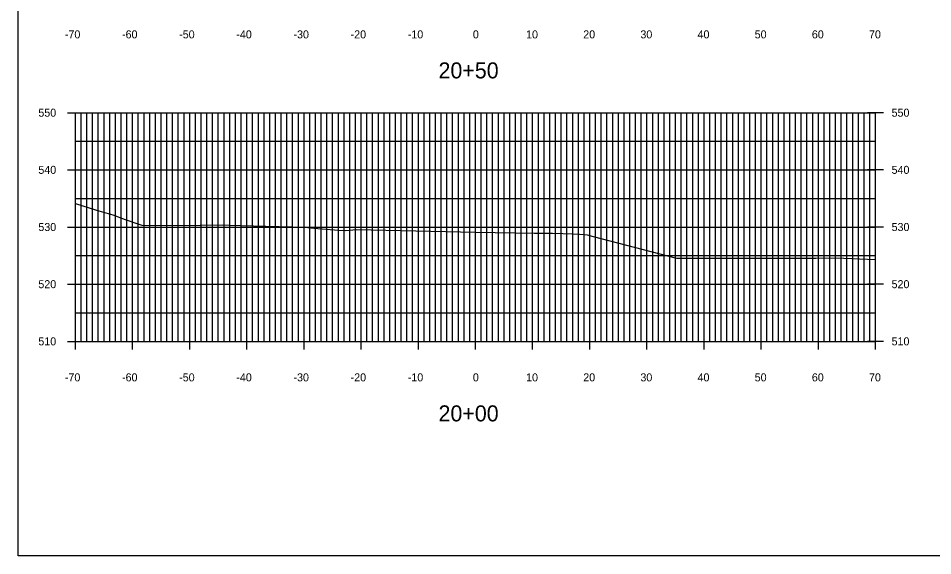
# Model space of a CAD drawing. Extents: x 1509063 to 1512863, y 401160 to 402918.
# Drawn here: x 1510250.9 to 1510410.9, y 402707.9 to 402801.9 of the extents above; entities that cross this region are included whole.
import ezdxf

# ---------------------------------------------------------------- set-up
doc = ezdxf.new("R2010")
doc.units = 0
for name, color, linetype in [('NBL1', 7, 'Continuous'), ('XAX_P', 7, 'Continuous'), ('XAXTIC_P', 7, 'Continuous'), ('XAXTXT_P_T', 7, 'Continuous'), ('XGL_P', 7, 'Continuous'), ('XSLOG', 7, 'Continuous')]:
    doc.layers.add(name, color=color, linetype=linetype)

msp = doc.modelspace()

# ---------------------------------------------------------------- linework, layer by layer
at = {"layer": 'NBL1'}
msp.add_lwpolyline([(1510570.91, 402707.91), (1510250.91, 402707.91), (1510250.91, 402917.91), (1510570.91, 402917.91)], close=True, dxfattribs=at)
at = {"layer": 'XAX_P'}
for p, q in [((1510260.91, 402745.41), (1510260.91, 402785.41)), ((1510330.91, 402745.41), (1510330.91, 402785.41)), ((1510400.91, 402745.41), (1510400.91, 402785.41)), ((1510260.91, 402745.41), (1510400.91, 402745.41))]:
    msp.add_line(p, q, dxfattribs=at)
at = {"layer": 'XAXTIC_P'}
for p, q in [((1510259.51, 402785.41), (1510262.31, 402785.41)), ((1510329.51, 402785.41), (1510332.31, 402785.41)), ((1510402.31, 402785.41), (1510399.51, 402785.41)), ((1510259.51, 402775.41), (1510262.31, 402775.41)), ((1510329.51, 402775.41), (1510332.31, 402775.41)), ((1510402.31, 402775.41), (1510399.51, 402775.41)), ((1510259.51, 402765.41), (1510262.31, 402765.41)), ((1510329.51, 402765.41), (1510332.31, 402765.41)), ((1510402.31, 402765.41), (1510399.51, 402765.41)), ((1510259.51, 402755.41), (1510262.31, 402755.41)), ((1510329.51, 402755.41), (1510332.31, 402755.41)), ((1510402.31, 402755.41), (1510399.51, 402755.41)), ((1510260.91, 402744.01), (1510260.91, 402746.81)), ((1510270.91, 402744.01), (1510270.91, 402746.81)), ((1510280.91, 402744.01), (1510280.91, 402746.81)), ((1510290.91, 402744.01), (1510290.91, 402746.81)), ((1510300.91, 402744.01), (1510300.91, 402746.81)), ((1510310.91, 402744.01), (1510310.91, 402746.81)), ((1510320.91, 402744.01), (1510320.91, 402746.81)), ((1510330.91, 402744.01), (1510330.91, 402746.81)), ((1510340.91, 402744.01), (1510340.91, 402746.81)), ((1510350.91, 402744.01), (1510350.91, 402746.81)), ((1510360.91, 402744.01), (1510360.91, 402746.81)), ((1510370.91, 402744.01), (1510370.91, 402746.81)), ((1510380.91, 402744.01), (1510380.91, 402746.81)), ((1510390.91, 402744.01), (1510390.91, 402746.81)), ((1510400.91, 402744.01), (1510400.91, 402746.81)), ((1510259.51, 402745.41), (1510262.31, 402745.41)), ((1510329.51, 402745.41), (1510332.31, 402745.41)), ((1510402.31, 402745.41), (1510399.51, 402745.41))]:
    msp.add_line(p, q, dxfattribs=at)
at = {"layer": 'XGL_P'}
for p, q in [((1510260.91, 402785.41), (1510400.91, 402785.41)), ((1510260.91, 402745.41), (1510260.91, 402785.41)), ((1510261.91, 402745.41), (1510261.91, 402785.41)), ((1510262.91, 402745.41), (1510262.91, 402785.41)), ((1510263.91, 402745.41), (1510263.91, 402785.41)), ((1510264.91, 402745.41), (1510264.91, 402785.41)), ((1510265.91, 402745.41), (1510265.91, 402785.41)), ((1510266.91, 402745.41), (1510266.91, 402785.41)), ((1510267.91, 402745.41), (1510267.91, 402785.41)), ((1510268.91, 402745.41), (1510268.91, 402785.41)), ((1510269.91, 402745.41), (1510269.91, 402785.41)), ((1510270.91, 402745.41), (1510270.91, 402785.41)), ((1510271.91, 402745.41), (1510271.91, 402785.41)), ((1510272.91, 402745.41), (1510272.91, 402785.41)), ((1510273.91, 402745.41), (1510273.91, 402785.41)), ((1510274.91, 402745.41), (1510274.91, 402785.41)), ((1510275.91, 402745.41), (1510275.91, 402785.41)), ((1510276.91, 402745.41), (1510276.91, 402785.41)), ((1510277.91, 402745.41), (1510277.91, 402785.41)), ((1510278.91, 402745.41), (1510278.91, 402785.41)), ((1510279.91, 402745.41), (1510279.91, 402785.41)), ((1510280.91, 402745.41), (1510280.91, 402785.41)), ((1510281.91, 402745.41), (1510281.91, 402785.41)), ((1510282.91, 402745.41), (1510282.91, 402785.41)), ((1510283.91, 402745.41), (1510283.91, 402785.41)), ((1510284.91, 402745.41), (1510284.91, 402785.41)), ((1510285.91, 402745.41), (1510285.91, 402785.41)), ((1510286.91, 402745.41), (1510286.91, 402785.41)), ((1510287.91, 402745.41), (1510287.91, 402785.41)), ((1510288.91, 402745.41), (1510288.91, 402785.41)), ((1510289.91, 402745.41), (1510289.91, 402785.41)), ((1510290.91, 402745.41), (1510290.91, 402785.41)), ((1510291.91, 402745.41), (1510291.91, 402785.41)), ((1510292.91, 402745.41), (1510292.91, 402785.41)), ((1510293.91, 402745.41), (1510293.91, 402785.41)), ((1510294.91, 402745.41), (1510294.91, 402785.41)), ((1510295.91, 402745.41), (1510295.91, 402785.41)), ((1510296.91, 402745.41), (1510296.91, 402785.41)), ((1510297.91, 402745.41), (1510297.91, 402785.41)), ((1510298.91, 402745.41), (1510298.91, 402785.41)), ((1510299.91, 402745.41), (1510299.91, 402785.41)), ((1510300.91, 402745.41), (1510300.91, 402785.41)), ((1510301.91, 402745.41), (1510301.91, 402785.41)), ((1510302.91, 402745.41), (1510302.91, 402785.41)), ((1510303.91, 402745.41), (1510303.91, 402785.41)), ((1510304.91, 402745.41), (1510304.91, 402785.41)), ((1510305.91, 402745.41), (1510305.91, 402785.41)), ((1510306.91, 402745.41), (1510306.91, 402785.41)), ((1510307.91, 402745.41), (1510307.91, 402785.41)), ((1510308.91, 402745.41), (1510308.91, 402785.41)), ((1510309.91, 402745.41), (1510309.91, 402785.41)), ((1510310.91, 402745.41), (1510310.91, 402785.41)), ((1510311.91, 402745.41), (1510311.91, 402785.41)), ((1510312.91, 402745.41), (1510312.91, 402785.41)), ((1510313.91, 402745.41), (1510313.91, 402785.41)), ((1510314.91, 402745.41), (1510314.91, 402785.41)), ((1510315.91, 402745.41), (1510315.91, 402785.41)), ((1510316.91, 402745.41), (1510316.91, 402785.41)), ((1510317.91, 402745.41), (1510317.91, 402785.41)), ((1510318.91, 402745.41), (1510318.91, 402785.41)), ((1510319.91, 402745.41), (1510319.91, 402785.41)), ((1510320.91, 402745.41), (1510320.91, 402785.41)), ((1510321.91, 402745.41), (1510321.91, 402785.41)), ((1510322.91, 402745.41), (1510322.91, 402785.41)), ((1510323.91, 402745.41), (1510323.91, 402785.41)), ((1510324.91, 402745.41), (1510324.91, 402785.41)), ((1510325.91, 402745.41), (1510325.91, 402785.41)), ((1510326.91, 402745.41), (1510326.91, 402785.41)), ((1510327.91, 402745.41), (1510327.91, 402785.41)), ((1510328.91, 402745.41), (1510328.91, 402785.41)), ((1510329.91, 402745.41), (1510329.91, 402785.41)), ((1510330.91, 402745.41), (1510330.91, 402785.41)), ((1510331.91, 402745.41), (1510331.91, 402785.41)), ((1510332.91, 402745.41), (1510332.91, 402785.41)), ((1510333.91, 402745.41), (1510333.91, 402785.41)), ((1510334.91, 402745.41), (1510334.91, 402785.41)), ((1510335.91, 402745.41), (1510335.91, 402785.41)), ((1510336.91, 402745.41), (1510336.91, 402785.41)), ((1510337.91, 402745.41), (1510337.91, 402785.41)), ((1510338.91, 402745.41), (1510338.91, 402785.41)), ((1510339.91, 402745.41), (1510339.91, 402785.41)), ((1510340.91, 402745.41), (1510340.91, 402785.41)), ((1510341.91, 402745.41), (1510341.91, 402785.41)), ((1510342.91, 402745.41), (1510342.91, 402785.41)), ((1510343.91, 402745.41), (1510343.91, 402785.41)), ((1510344.91, 402745.41), (1510344.91, 402785.41)), ((1510345.91, 402745.41), (1510345.91, 402785.41)), ((1510346.91, 402745.41), (1510346.91, 402785.41)), ((1510347.91, 402745.41), (1510347.91, 402785.41)), ((1510348.91, 402745.41), (1510348.91, 402785.41)), ((1510349.91, 402745.41), (1510349.91, 402785.41)), ((1510350.91, 402745.41), (1510350.91, 402785.41)), ((1510351.91, 402745.41), (1510351.91, 402785.41)), ((1510352.91, 402745.41), (1510352.91, 402785.41)), ((1510353.91, 402745.41), (1510353.91, 402785.41)), ((1510354.91, 402745.41), (1510354.91, 402785.41)), ((1510355.91, 402745.41), (1510355.91, 402785.41)), ((1510356.91, 402745.41), (1510356.91, 402785.41)), ((1510357.91, 402745.41), (1510357.91, 402785.41)), ((1510358.91, 402745.41), (1510358.91, 402785.41)), ((1510359.91, 402745.41), (1510359.91, 402785.41)), ((1510360.91, 402745.41), (1510360.91, 402785.41)), ((1510361.91, 402745.41), (1510361.91, 402785.41)), ((1510362.91, 402745.41), (1510362.91, 402785.41)), ((1510363.91, 402745.41), (1510363.91, 402785.41)), ((1510364.91, 402745.41), (1510364.91, 402785.41)), ((1510365.91, 402745.41), (1510365.91, 402785.41)), ((1510366.91, 402745.41), (1510366.91, 402785.41)), ((1510367.91, 402745.41), (1510367.91, 402785.41)), ((1510368.91, 402745.41), (1510368.91, 402785.41)), ((1510369.91, 402745.41), (1510369.91, 402785.41)), ((1510370.91, 402745.41), (1510370.91, 402785.41)), ((1510371.91, 402745.41), (1510371.91, 402785.41)), ((1510372.91, 402745.41), (1510372.91, 402785.41)), ((1510373.91, 402745.41), (1510373.91, 402785.41)), ((1510374.91, 402745.41), (1510374.91, 402785.41)), ((1510375.91, 402745.41), (1510375.91, 402785.41)), ((1510376.91, 402745.41), (1510376.91, 402785.41)), ((1510377.91, 402745.41), (1510377.91, 402785.41)), ((1510378.91, 402745.41), (1510378.91, 402785.41)), ((1510379.91, 402745.41), (1510379.91, 402785.41)), ((1510380.91, 402745.41), (1510380.91, 402785.41)), ((1510381.91, 402745.41), (1510381.91, 402785.41)), ((1510382.91, 402745.41), (1510382.91, 402785.41)), ((1510383.91, 402745.41), (1510383.91, 402785.41)), ((1510384.91, 402745.41), (1510384.91, 402785.41)), ((1510385.91, 402745.41), (1510385.91, 402785.41)), ((1510386.91, 402745.41), (1510386.91, 402785.41)), ((1510387.91, 402745.41), (1510387.91, 402785.41)), ((1510388.91, 402745.41), (1510388.91, 402785.41)), ((1510389.91, 402745.41), (1510389.91, 402785.41)), ((1510390.91, 402745.41), (1510390.91, 402785.41)), ((1510391.91, 402745.41), (1510391.91, 402785.41)), ((1510392.91, 402745.41), (1510392.91, 402785.41)), ((1510393.91, 402745.41), (1510393.91, 402785.41)), ((1510394.91, 402745.41), (1510394.91, 402785.41)), ((1510395.91, 402745.41), (1510395.91, 402785.41)), ((1510396.91, 402745.41), (1510396.91, 402785.41)), ((1510397.91, 402745.41), (1510397.91, 402785.41)), ((1510398.91, 402745.41), (1510398.91, 402785.41)), ((1510399.91, 402745.41), (1510399.91, 402785.41)), ((1510400.91, 402745.41), (1510400.91, 402785.41)), ((1510260.91, 402780.41), (1510400.91, 402780.41)), ((1510260.91, 402775.41), (1510400.91, 402775.41)), ((1510260.91, 402770.41), (1510400.91, 402770.41)), ((1510260.91, 402765.41), (1510400.91, 402765.41)), ((1510260.91, 402760.41), (1510400.91, 402760.41)), ((1510260.91, 402755.41), (1510400.91, 402755.41)), ((1510260.91, 402750.41), (1510400.91, 402750.41)), ((1510260.91, 402745.41), (1510400.91, 402745.41))]:
    msp.add_line(p, q, dxfattribs=at)
at = {"layer": 'XSLOG'}
msp.add_lwpolyline([(1510260.91, 402769.52), (1510264.62, 402768.35), (1510267.48, 402767.54), (1510269.63, 402766.73), (1510271.63, 402766.03), (1510272.5, 402765.75), (1510272.98, 402765.65), (1510282.73, 402765.76), (1510286.61, 402765.8), (1510287.8, 402765.75), (1510294.23, 402765.57), (1510298.97, 402765.42), (1510300.32, 402765.38), (1510301.07, 402765.36), (1510302.6, 402765.2), (1510306.92, 402764.87), (1510308.22, 402764.8), (1510310.05, 402764.99), (1510330.91, 402764.51), (1510341.22, 402764.36), (1510344.36, 402764.32), (1510347.97, 402764.2), (1510349.08, 402764.17), (1510350.46, 402764.06), (1510351.5, 402763.75), (1510366.06, 402759.97), (1510370.72, 402759.98), (1510390.43, 402759.99), (1510393.93, 402760), (1510400.91, 402759.74)], dxfattribs=at)

# ---------------------------------------------------------------- texts
at = {"layer": 'XAXTXT_P_T'}
for s, height, p in [('-70', 1.4, (1510259.06, 402798.41)), ('-60', 1.4, (1510269.06, 402798.41)), ('-50', 1.4, (1510279.06, 402798.41)), ('-40', 1.4, (1510289.06, 402798.41)), ('-30', 1.4, (1510299.06, 402798.41)), ('-20', 1.4, (1510309.06, 402798.41)), ('-10', 1.4, (1510319.06, 402798.41)), ('0', 1.4, (1510330.45, 402798.41)), ('10', 1.4, (1510339.76, 402798.41)), ('20', 1.4, (1510349.76, 402798.41)), ('30', 1.4, (1510359.76, 402798.41)), ('40', 1.4, (1510369.76, 402798.41)), ('50', 1.4, (1510379.76, 402798.41)), ('60', 1.4, (1510389.76, 402798.41)), ('70', 1.4, (1510399.76, 402798.41)), ('20+50', 2.8, (1510324.44, 402791.41)), ('550', 1.4, (1510254.42, 402784.71)), ('550', 1.4, (1510403.71, 402784.71)), ('540', 1.4, (1510254.42, 402774.71)), ('540', 1.4, (1510403.71, 402774.71)), ('530', 1.4, (1510254.42, 402764.71)), ('530', 1.4, (1510403.71, 402764.71)), ('520', 1.4, (1510254.42, 402754.71)), ('520', 1.4, (1510403.71, 402754.71)), ('510', 1.4, (1510254.42, 402744.71)), ('510', 1.4, (1510403.71, 402744.71)), ('-70', 1.4, (1510259.06, 402738.41)), ('-60', 1.4, (1510269.06, 402738.41)), ('-50', 1.4, (1510279.06, 402738.41)), ('-40', 1.4, (1510289.06, 402738.41)), ('-30', 1.4, (1510299.06, 402738.41)), ('-20', 1.4, (1510309.06, 402738.41)), ('-10', 1.4, (1510319.06, 402738.41)), ('0', 1.4, (1510330.45, 402738.41)), ('10', 1.4, (1510339.76, 402738.41)), ('20', 1.4, (1510349.76, 402738.41)), ('30', 1.4, (1510359.76, 402738.41)), ('40', 1.4, (1510369.76, 402738.41)), ('50', 1.4, (1510379.76, 402738.41)), ('60', 1.4, (1510389.76, 402738.41)), ('70', 1.4, (1510399.76, 402738.41)), ('20+00', 2.8, (1510324.44, 402731.41))]:
    msp.add_text(s, height=height, dxfattribs=at).set_placement(p)

doc.saveas('drawing.dxf')
